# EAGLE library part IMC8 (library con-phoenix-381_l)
Invertierter Mini-Combicon 3.81mm horizontal 8-polig IMC 1,5/8-G-3,81 (ohne Gegenstecker)
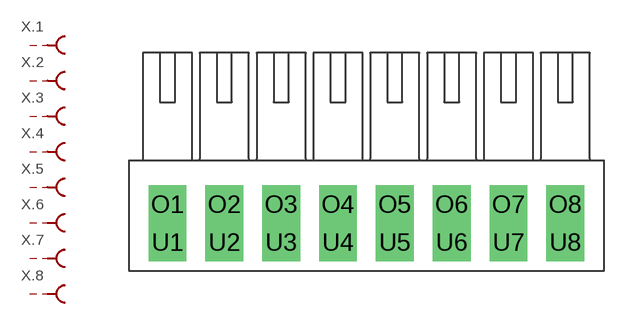
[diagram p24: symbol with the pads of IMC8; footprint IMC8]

Designator prefix X; gates .4=MCBU .3=MCBU .2=MCBU .1=MCBU .5=MCBU .6=MCBU .7=MCBU .8=MCBU

## IMC8  [IMC8]
O1  .1:S  pas
O2  .2:S  pas
O3  .3:S  pas
O4  .4:S  pas
O5  .5:S  pas
O6  .6:S  pas
O7  .7:S  pas
O8  .8:S  pas
U1  .1:SK  pas
U2  .2:SK  pas
U3  .3:SK  pas
U4  .4:SK  pas
U5  .5:SK  pas
U6  .6:SK  pas
U7  .7:SK  pas
U8  .8:SK  pas

## Footprint IMC8 (pad centres in mm)
Mini-Combicon 3.81mm horizontal 8-polig invertiert (ohne Gegenstecker)
drill 1.3 pad 2.54 square: O1 -13.335,1.27; O2 -9.525,1.27; O3 -5.715,1.27; O4 -1.905,1.27; O5 1.905,1.27; O6 5.715,1.27; O7 9.525,1.27; O8 13.335,1.27; U1 -13.335,-1.27; U2 -9.525,-1.27; U3 -5.715,-1.27; U4 -1.905,-1.27; U5 1.905,-1.27; U6 5.715,-1.27; U7 9.525,-1.27; U8 13.335,-1.27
